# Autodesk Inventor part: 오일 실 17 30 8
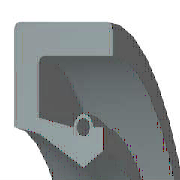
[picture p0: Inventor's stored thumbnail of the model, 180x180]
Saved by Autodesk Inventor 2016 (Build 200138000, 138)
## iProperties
IsCustomPart: 1
Created: 2012-02
Part Number: 오일 실 17 30 8
Material: 고무
Description: 오일-실
Document SubType Name: Modeling
Standard: KS B 2804
Designer: mduedu
Standards Organization: KS
Language: ko-KR
Size Designation: S - 17 30 8
Categories: <MemberInstance><Categories><Category DisplayName="샤프트 부품" InternalName="7f7aeb1f-a693-4053-b835-cee3144e0d98" Mnemonic="SHFT"><Category DisplayName="실링" Intern
Density: 0.93 g/cm^3
Appearance: 고무 - 검은색 - 버전 1.1
Author: mduedu
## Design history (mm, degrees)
revolve "본체" stored, may be unused: angle "d17" = 90 deg
revolve "스프링1" stored, may be unused: angle "d18" = 90 deg
body "Solid1"
sketch "스케치1"
  geometry: L1 (0, 15)-(8, 15); L2 (8, 15)-(8, 13.75); L3 (8, 13.75)-(1.75, 13.75); L4 (0, 15)-(0, 10.6); L5 (0, 10.6)-(1.75, 10.25); L6 (1.75, 10.25)-(4.9, 8.5); L7 (4.9, 8.5)-(0, 8.5); L8 (6.3, 9.375)-(6.3, 10.6); L9 (0, 0)-(9.586, 0) reference; L10 (4.9, 8.5)-(6.3, 9.375); L11 (0, 18)-(0, -3) reference; L12 (-1.917, 0)-(11.503, 0) reference; L13 (4.2, 10.6)-(1.75, 11.09); L14 (1.75, 11.09)-(1.75, 13.75); L15 (6.3, 10.6)-(5.6, 10.6); C1 r 0.455 at (4.9, 10.6); A1 r 0.7 centre (4.9, 10.6) between (5.6, 10.6) and (4.2, 10.6)
  constraints: 26 end point, 5 horizontal alignment, 4 perpendicular, 2 centre point, 2 collinear, 2 horizontal, 2 parallel, 2 point on circle, 2 point on line, 2 vertical alignment, 1 coincident
  dimensions: "d0" = 30 diameter of L1 L9 (= SD2); "d1" = 18.75 diameter of L8.start L9 (= ABDM); "d2" = 1.25 distance of L1.end L2.end (computed from SD); "d3" = 0.91 diameter of C1 (= SPDI); "d4" = 1.4 diameter of A1 (= SPDA); "d5" = 17 diameter of L6.end L9 (= NND); "d6" = 20.5 diameter of L5.end L9 (= TKDM); "d7" = 21.2 diameter of L4.end L9 (= HLDM); "d8" = 4.9 distance from line of C1.centre L4 (= SPDST); "d9" = 6.3 distance between parallel lines of L8 L4 (= SDI); "d10" = 8 distance between parallel lines of L2 L4 (= SWDT); "d12" = 1.75 distance between parallel lines of L14 L4 (= SD)
fillet "모깎기1" dims "d11" = 0.5 (= RR)
other parameters: "SD2" = 30 [user parameter; used in 1 equation term], "SWDT" = 8 [user parameter; used in 1 equation term], "RR" = 0.5 [user parameter; used in 1 equation term], "SD" = 1.75 [user parameter; used in 2 equation terms], "NND" = 17 [user parameter; used in 1 equation term], "SPDA" = 1.4 [user parameter; used in 1 equation term], "SPDI" = 0.91 [user parameter; used in 1 equation term], "TKDM" = 20.5 [user parameter; used in 1 equation term], "HLDM" = 21.2 [user parameter; used in 1 equation term], "ABDM" = 18.75 [user parameter; used in 1 equation term], "SDI" = 6.3 [user parameter; used in 1 equation term], "SPDST" = 4.9 [user parameter; used in 1 equation term], "d13" = 0, "d14" = 0, "d15" = 0, "LAB" = 0.35 [user parameter]
